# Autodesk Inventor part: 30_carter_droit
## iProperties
Created: 2002-11
Part Number: 30_carter_droit
Material: Par défaut
Document SubType Name: Modélisation
Designer: poste-2
Control State: 0
Master: False
Checked Out: False
Shininess: 41.0
Length Units: 11269
Angle Units: 11279
Time Units: 11290
Mass Units: 11283
Length Display Precision: 3
Angle Display Precision: 2
Compacted: True
Density: 0.0
Volumn: 0.0
Area: 0.0
PropertySet Name: Model Information
Author: poste-2
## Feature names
1. Extrusion1
2. Balayage1
3. Symétrie1 [Mirror]
4. Extrusion2
5. Extrusion3
6. Extrusion4
7. Congé1 [Fillet]
8. Extrusion8
9. Extrusion9
10. Extrusion10
11. Extrusion11
12. Chanfrein1 [Chamfer]
13. Extrusion12
14. Extrusion13
15. Extrusion14
16. Extrusion15
17. Extrusion16
18. Extrusion17
19. Extrusion18
20. Extrusion19
21. Extrusion21
22. Extrusion22
23. Extrusion23
24. Réseau rectangulaire1 [Rectangular Pattern]
25. Extrusion24
26. Extrusion25
27. Extrusion26
28. Réseau rectangulaire2 [Rectangular Pattern]
29. Extrusion27
30. Extrusion28
31. Réseau rectangulaire3 [Rectangular Pattern]
32. Extrusion29
33. Extrusion30
34. Révolution1 [Revolution]
35. Réseau rectangulaire4 [Rectangular Pattern]
36. Extrusion31
37. Extrusion32
38. Extrusion33
39. Extrusion35
40. Extrusion36
41. Extrusion37
42. Extrusion38
43. Extrusion39
44. Extrusion40
45. Extrusion41
46. Extrusion44
47. Extrusion45
48. Réseau rectangulaire5 [Rectangular Pattern]
49. Extrusion46
50. Extrusion6
51. Extrusion7
52. Congé2 [Fillet]
53. Extrusion47
54. Extrusion48
55. Extrusion49
